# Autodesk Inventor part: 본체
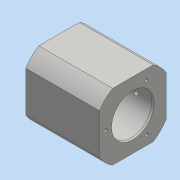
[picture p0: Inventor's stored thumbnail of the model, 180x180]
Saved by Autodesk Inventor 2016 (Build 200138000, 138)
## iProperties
Created: 2020-02
Part Number: 본체
Material: 일반
Document SubType Name: Modeling
Designer: Administrator
Density: 1 g/cm^3
Appearance: 기본값
Mass: 199.224 g
Surface Area: 342.681 cm^2
Volume: 199.224 cm^3
Author: Administrator
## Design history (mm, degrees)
sketch "스케치1"
  geometry: L1 (-19.551, 32)-(19.551, 32); L2 (32, 19.551)-(32, -19.551); L3 (19.551, -32)-(-19.551, -32); L4 (-32, -19.551)-(-32, 19.551); L5 (-32, 32)-(32, -32); L6 (32, 32)-(-32, -32); A1 r 37.5 centre (0, 0) between (19.551, -32) and (32, -19.551); A2 r 37.5 centre (0, 0) between (-32, -19.551) and (-19.551, -32); A3 r 37.5 centre (0, 0) between (32, 19.551) and (19.551, 32); A4 r 37.5 centre (0, 0) between (-19.551, 32) and (-32, 19.551); 1 further point
  constraints: 12 end point, 8 point on circle, 4 centre point, 2 midpoint, 2 parallel, 1 coincident, 1 horizontal, 1 perpendicular
  dimensions: "d0" = 64 distance of L6.start L5.end
extrude "돌출1" new body sketch "스케치1" distance "d2" = 71; taper "d3" = 0 deg
sketch "스케치2"
  geometry: C1 r 14 at (0, 0); 1 further point
  constraints: 1 centre point, 1 coincident
  dimensions: "d4" = 28 diameter of C1
extrude "돌출2" join sketch "스케치2" distance "d5" = 12; taper "d6" = 0 deg
hole "구멍1" diameter "d9" = 8.917; stored, may be unused: countersink angle "d13" = 90 deg, drill point angle "d15" = 118 deg; dims "d7" = 10, "d8" = 10, "d10" = 14, "d11" = 4, "d12" = 2, "d14" = 17
sketch "스케치3"
  geometry: C1 r 4.458 at (0, 0) reference; C2 r 20 at (0, 0); 1 further point
  constraints: 1 centre point, 1 coincident
  dimensions: "d16" = 40 diameter of C2
extrude "돌출3" cut sketch "스케치3" distance "d17" = 62; taper "d18" = 0 deg
sketch "스케치4"
  geometry: L1 (-37.283, 0)-(46.134, 0); L2 (0, 0)-(46.451, 26.819); L3 (0, 0)-(-47.571, 27.465); L4 (0, 0)-(0, 48.754); C1 r 4.458 at (0, 0) reference; A1 r 26 centre (0, 0) between (-22.517, 13) and (0, -26); 2 further points
  constraints: 8 end point, 2 point on circle, 1 centre point, 1 coincident, 1 horizontal, 1 midpoint, 1 point on line, 1 vertical
  dimensions: "d19" = 52 diameter of A1; "d20" = 60 deg angle of L4 L2; "d21" = 60 deg angle of L4 L3
hole "구멍2" sketch "스케치4" at (-22.517, 13), (23.226, 13.409), (0, -26) diameter "d22" = 3.242; stored, may be unused: countersink angle "d26" = 90 deg, drill point angle "d28" = 118 deg; dims "d23" = 10, "d24" = 4, "d25" = 2, "d27" = 12
chamfer "모따기1" distance "d36" = 1.8; stored, may be unused: second distance "d37" = 2, angle "d38" = 15 deg
chamfer "모따기2" distance "d39" = 1; stored, may be unused: second distance "d40" = 2, angle "d41" = 15 deg
sketch "스케치6"
  geometry: L1 (71, 39.102)-(71, 0) reference; L2 (0, 0)-(0, 39.102) reference; 3 further points
  constraints: 1 horizontal alignment, 1 midpoint
  dimensions: "d42" = 17 distance from line of L1 point (54, 19.551)
hole "구멍4" sketch "스케치6" at (54, 19.551) diameter "d43" = 8.917; stored, may be unused: countersink angle "d47" = 90 deg, drill point angle "d49" = 118 deg; dims "d44" = 6, "d45" = 4, "d46" = 2, "d48" = 9
sketch "스케치7"
  geometry: C1 r 4.458 at (54, 19.551) reference; C2 r 2 at (54, 19.551); 1 further point
  constraints: 1 centre point, 1 coincident
  dimensions: "d50" = 4 diameter of C2
extrude "돌출4" cut sketch "스케치7" distance "d51" = 20; taper "d52" = 0 deg
sketch "스케치8"
  geometry: C1 r 4.458 at (0, 0) reference; C2 r 2 at (0, 0); 1 further point
  constraints: 1 centre point, 1 coincident
  dimensions: "d53" = 4 diameter of C2
extrude "돌출5" cut sketch "스케치8" distance "d54" = 40; taper "d55" = 0 deg
sketch "스케치9"
  geometry: L1 (0, 0)-(0, 39.102) reference; 3 further points
  constraints: 1 horizontal alignment, 1 midpoint, 1 other
  dimensions: "d56" = 20 distance from line of L1 point (20, 19.551)
feature "엠보싱1" sketch "스케치9" dims "d57" = 0.5, "d58" = 0
sketch "스케치10"
  geometry: C1 r 14 at (0, 0) reference; C2 r 2 at (0, 0) reference; C3 r 1.621 at (0, -26) reference; A1 r 26 centre (0, 0) between (-26, 0) and (0, 26); 3 further points
  constraints: 3 point on circle, 2 coincident, 1 centre point
  dimensions: "d59" = 52 diameter of A1
hole "구멍5" sketch "스케치10" at (-26, 0), (0, 26), (26, 0), (0, -26) diameter "d60" = 3.242; stored, may be unused: countersink angle "d64" = 90 deg, drill point angle "d66" = 118 deg; dims "d61" = 10, "d62" = 4, "d63" = 2, "d65" = 12
node "솔리드1"
other parameters: "d1" = 75
